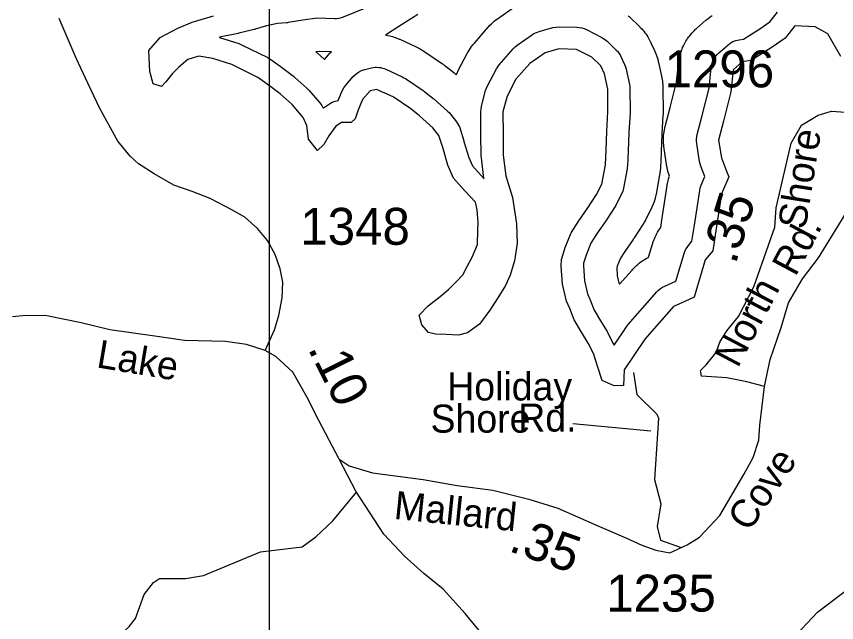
# Model space of a CAD drawing. Extents: x 1113032 to 1302912, y 664689 to 832535.
# Drawn here: x 1146811 to 1149593, y 736082 to 738136 of the extents above; entities that cross this region are included whole.
import ezdxf

# ---------------------------------------------------------------- set-up
doc = ezdxf.new("R2010")
doc.units = 0
for name, color, linetype in [('Exist Hydrographic Buffer Line', 7, 'Continuous'), ('Exist Hydrographic Lake Shore', 7, 'Continuous'), ('Exist Road Non-System Type 51', 7, 'Continuous'), ('Exist Road Non-System Type 51 Label', 7, 'Continuous'), ('Exist Road Secondary Mileage Hundredths English Label', 7, 'Continuous'), ('Exist Road Secondary Type 51 Attributed', 7, 'Continuous'), ('Exist Road Secondary Type 51 Label', 7, 'Continuous'), ('Exist Road Secondary Type 51 Number Label', 7, 'Continuous'), ('Map Preparation Inset Cut Line', 7, 'Continuous')]:
    doc.layers.add(name, color=color, linetype=linetype)

msp = doc.modelspace()

# ---------------------------------------------------------------- linework, layer by layer
at = {"layer": 'Exist Hydrographic Buffer Line'}
for points in [[(1147992, 738162.3), (1147919, 738133.4), (1147911.9, 738130.9), (1147904.6, 738129.2), (1147897.1, 738128.3), (1147889.6, 738128.1), (1147830.9, 738129.5), (1147782.4, 738122.7), (1147733.1, 738114.9), (1147730.6, 738114.6), (1147728.2, 738114.3), (1147696.8, 738111.5), (1147659.3, 738103.6), (1147621.2, 738092.4), (1147619.5, 738091.9), (1147617.7, 738091.4), (1147565.3, 738078.7), (1147564, 738078.4), (1147562.6, 738078.1), (1147499.4, 738065.2), (1147500.2, 738065), (1147564.9, 738043.8), (1147569.7, 738042), (1147574.4, 738039.9), (1147663.1, 737996.5), (1147668.6, 737993.5), (1147673.9, 737990.1), (1147712.9, 737962.1), (1147713.7, 737961.5), (1147714.5, 737960.9), (1147750.9, 737933.3), (1147753.4, 737931.4), (1147755.7, 737929.4), (1147795.8, 737893.4), (1147799.3, 737890), (1147802.6, 737886.4), (1147840.1, 737842.8), (1147846.5, 737834), (1147851.1, 737825.5), (1147852.8, 737826.7), (1147872.7, 737839.8), (1147882.2, 737845.1), (1147892.4, 737849), (1147901.8, 737851.1), (1147916.3, 737884.2), (1147921.6, 737894.2), (1147928.3, 737903.2), (1147953.5, 737932.4), (1147961.8, 737940.5), (1147971.1, 737947.2), (1147981.4, 737952.5), (1147992.4, 737956.1), (1148014.7, 737961.6), (1148020.9, 737962.8), (1148027.2, 737963.5), (1148033.5, 737963.7), (1148039.8, 737963.4), (1148046.1, 737962.5), (1148052.2, 737961.1), (1148058.3, 737959.2), (1148064.1, 737956.8), (1148119.8, 737931), (1148125.1, 737928.3), (1148130.2, 737925.1), (1148190.3, 737884.6), (1148192.6, 737883), (1148194.9, 737881.3), (1148224.8, 737857.6), (1148226.3, 737856.4), (1148227.8, 737855.1), (1148273.1, 737815.2), (1148278.2, 737810.3), (1148282.8, 737804.9), (1148303.2, 737778.7), (1148307.1, 737773.2), (1148310.4, 737767.5), (1148313.3, 737761.4), (1148315.5, 737755.2), (1148328.5, 737714.1), (1148328.7, 737713.4), (1148328.9, 737712.7), (1148344.9, 737657.9), (1148357.5, 737629.5), (1148386.7, 737597), (1148396.9, 737585.8), (1148396.7, 737587), (1148387.9, 737656.6), (1148387.5, 737660.8), (1148387.3, 737665), (1148386.4, 737735.9), (1148386.3, 737736.4), (1148386.3, 737736.8), (1148386.2, 737812.5), (1148386.8, 737822), (1148388.6, 737831.4), (1148402.4, 737884.4), (1148405, 737892.7), (1148408.6, 737900.6), (1148438.8, 737957.8), (1148443.3, 737965.3), (1148448.6, 737972.2), (1148495.5, 738026), (1148502, 738032.6), (1148509.3, 738038.4), (1148561, 738074.2), (1148566.3, 738077.6), (1148571.9, 738080.5), (1148577.7, 738083), (1148583.7, 738084.9), (1148630.3, 738097.9), (1148641.1, 738100), (1148652, 738100.6), (1148712.1, 738099.3), (1148720.5, 738098.7), (1148728.7, 738097.1), (1148736.7, 738094.6), (1148744.4, 738091.2), (1148796.1, 738065), (1148805.7, 738059.2), (1148814.3, 738052), (1148845.4, 738021.9), (1148850.1, 738016.9), (1148854.3, 738011.5), (1148858, 738005.8), (1148861.2, 737999.7), (1148873.6, 737973), (1148876.8, 737965.2), (1148879, 737957), (1148890, 737905.4), (1148891.2, 737898), (1148891.6, 737890.4), (1148892.2, 737814.3), (1148892.2, 737811.6), (1148892.1, 737808.9), (1148887.8, 737742.3), (1148885.7, 737680.8), (1148885.7, 737680.3), (1148885.7, 737679.8), (1148883.2, 737629.6), (1148882.8, 737624.7), (1148882.1, 737619.8), (1148870.1, 737554.1), (1148867.4, 737543.6), (1148863.2, 737533.5), (1148845.5, 737498.8), (1148843.6, 737495.3), (1148841.5, 737491.8), (1148811.9, 737446.6), (1148811.3, 737445.6), (1148810.6, 737444.7), (1148780.8, 737401.9), (1148759.1, 737367.9), (1148742.9, 737327.6), (1148734.3, 737300.2), (1148734.1, 737291), (1148737.1, 737240.1), (1148747.7, 737196.3), (1148756, 737178.4), (1148757.3, 737175.6), (1148758.4, 737172.8), (1148770.4, 737140.2), (1148791.6, 737104.9), (1148814.1, 737068.5), (1148815.7, 737065.7), (1148817.2, 737063), (1148835.3, 737027.5), (1148837.7, 737022.2), (1148837.8, 737022), (1148879.8, 737084.3), (1148882.6, 737088.2), (1148885.6, 737091.9), (1148983.1, 737202.9), (1148988.9, 737208.8), (1148995.3, 737214), (1149002.2, 737218.5), (1149009.5, 737222.2), (1149047.5, 737238.7), (1149075.5, 737332.8), (1149078.1, 737340), (1149081.4, 737347), (1149085.4, 737353.6), (1149090.1, 737359.8), (1149102.1, 737374), (1149110.5, 737428.8), (1149128.5, 737546.1), (1149130.4, 737555.2), (1149133.5, 737564), (1149146.1, 737593.8), (1149132.2, 737628.9), (1149129.7, 737636.7), (1149127.9, 737644.7), (1149118.3, 737705), (1149117.5, 737712.7), (1149117.4, 737720.3), (1149118.2, 737728), (1149119.7, 737735.5), (1149136.2, 737799.7), (1149160, 737893.3), (1149167.3, 737963.2), (1149168.3, 737970.1), (1149170, 737976.9), (1149172.3, 737983.5), (1149175.2, 737989.8), (1149178.7, 737995.9), (1149182.8, 738001.6), (1149187.3, 738006.9), (1149192.3, 738011.7), (1149223.2, 738038.9), (1149231.8, 738045.4), (1149241.2, 738050.7), (1149251.4, 738054.5), (1149261.9, 738056.8), (1149276.8, 738059), (1149332.4, 738094), (1149366.2, 738117.8), (1149392.7, 738150.8)], [(1148171.9, 738142.3), (1148107.8, 738102.1), (1148066, 738075), (1148063.7, 738073.5), (1148063.1, 738073.2), (1148066.2, 738072.7), (1148070.8, 738071.7), (1148077, 738070.3), (1148081.6, 738069.2), (1148086.1, 738067.9), (1148092.1, 738066), (1148096.6, 738064.4), (1148101, 738062.7), (1148106.8, 738060.3), (1148109, 738059.4), (1148111.2, 738058.4), (1148166.8, 738032.6), (1148168.9, 738031.7), (1148170.9, 738030.7), (1148176.2, 738028), (1148180.1, 738025.8), (1148183.9, 738023.6), (1148189, 738020.4), (1148190.9, 738019.2), (1148192.8, 738018), (1148252.9, 737977.5), (1148253.7, 737976.9), (1148254.6, 737976.3), (1148257, 737974.7), (1148258.7, 737973.4), (1148260.4, 737972.2), (1148262.7, 737970.4), (1148263.5, 737969.8), (1148264.4, 737969.1), (1148294.3, 737945.4), (1148294.9, 737945), (1148295.4, 737944.5), (1148297, 737943.3), (1148298.1, 737942.3), (1148299.2, 737941.4), (1148300.7, 737940.1), (1148301.3, 737939.6), (1148301.8, 737939.2), (1148302.8, 737938.3), (1148303.1, 737939), (1148306.7, 737946.9), (1148308, 737949.8), (1148309.5, 737952.7), (1148339.7, 738010), (1148341.2, 738012.8), (1148342.8, 738015.7), (1148347.3, 738023.1), (1148350.9, 738028.6), (1148354.7, 738033.8), (1148360, 738040.7), (1148362.1, 738043.3), (1148364.2, 738045.7), (1148411.1, 738099.6), (1148413.4, 738102.2), (1148415.8, 738104.7), (1148422.3, 738111.3), (1148427.3, 738116), (1148432.6, 738120.5), (1148439.9, 738126.2), (1148442.6, 738128.3), (1148445.4, 738130.4), (1148497.1, 738166.2)], [(1148886, 738138.1), (1148889.2, 738135.3), (1148892.3, 738132.5), (1148923.3, 738102.4), (1148925.1, 738100.6), (1148926.9, 738098.7), (1148931.6, 738093.7), (1148935.1, 738089.9), (1148938.3, 738086), (1148942.5, 738080.6), (1148945.6, 738076.5), (1148948.5, 738072.2), (1148952.2, 738066.5), (1148954.9, 738062.1), (1148957.3, 738057.6), (1148960.5, 738051.5), (1148961.7, 738049.3), (1148962.8, 738046.9), (1148975.2, 738020.3), (1148976.5, 738017.4), (1148977.7, 738014.5), (1148980.8, 738006.6), (1148983, 738000.7), (1148984.8, 737994.6), (1148987, 737986.4), (1148987.8, 737983.4), (1148988.5, 737980.3), (1148999.5, 737928.7), (1149000.1, 737926), (1149000.5, 737923.2), (1149001.7, 737915.7), (1149002.5, 737910.1), (1149003, 737904.5), (1149003.4, 737897), (1149003.5, 737894.1), (1149003.6, 737891.3), (1149004.2, 737815.2), (1149004.2, 737814.2), (1149004.2, 737813.2), (1149004.2, 737810.5), (1149004.1, 737808.5), (1149004.1, 737806.5), (1149003.9, 737803.8), (1149003.9, 737802.8), (1149003.8, 737801.8), (1148999.7, 737736.8), (1148997.6, 737677), (1148997.6, 737676.8), (1148997.6, 737676.6), (1148997.6, 737676), (1148997.6, 737675.6), (1148997.6, 737675.2), (1148997.6, 737674.7), (1148997.5, 737674.5), (1148997.5, 737674.3), (1148995.1, 737624.1), (1148995, 737622.3), (1148994.8, 737620.5), (1148994.4, 737615.6), (1148994.1, 737611.9), (1148993.6, 737608.2), (1148992.9, 737603.4), (1148992.6, 737601.6), (1148992.3, 737599.7), (1148980.3, 737534), (1148979.5, 737530), (1148978.5, 737526.1), (1148975.8, 737515.5), (1148973.5, 737507.8), (1148970.6, 737500.2), (1148966.4, 737490.2), (1148964.8, 737486.5), (1148963, 737482.8), (1148945.4, 737448.1), (1148944.7, 737446.8), (1148944, 737445.4), (1148942, 737441.8), (1148940.5, 737439.2), (1148939, 737436.6), (1148936.9, 737433.1), (1148936.1, 737431.8), (1148935.2, 737430.6), (1148905.7, 737385.4), (1148905.5, 737385), (1148905.2, 737384.6), (1148904.6, 737383.7), (1148904.1, 737382.9), (1148903.6, 737382.2), (1148902.9, 737381.2), (1148902.7, 737380.9), (1148902.4, 737380.5), (1148874, 737339.8), (1148859.2, 737316.5), (1148848.5, 737290), (1148846.7, 737284.2), (1148848.3, 737256.7), (1148853.9, 737233.5), (1148856.3, 737228.3), (1148899, 737276.8), (1148901.1, 737279.1), (1148903.2, 737281.3), (1148908.9, 737287.2), (1148913.4, 737291.5), (1148918, 737295.5), (1148924.4, 737300.7), (1148929.2, 737304.4), (1148934.3, 737307.9), (1148941.2, 737312.4), (1148946.4, 737315.6), (1148951.8, 737318.5), (1148954.8, 737320), (1148968.1, 737364.7), (1148969, 737367.5), (1148969.9, 737370.2), (1148972.5, 737377.5), (1148974.6, 737382.9), (1148976.9, 737388.2), (1148980.2, 737395.1), (1148982.8, 737400.3), (1148985.7, 737405.3), (1148989.7, 737411.9), (1148992.8, 737416.7), (1148996, 737421.1), (1148999.8, 737445.8), (1149017.8, 737563), (1149018.3, 737566.4), (1149019, 737569.9), (1149021, 737578.9), (1149022.7, 737585.7), (1149024.8, 737592.3), (1149025.6, 737594.7), (1149023.4, 737601.3), (1149021.6, 737607.1), (1149020.2, 737613), (1149018.5, 737621), (1149017.9, 737624), (1149017.3, 737627), (1149007.7, 737687.4), (1149007.3, 737690.2), (1149006.9, 737693), (1149006.1, 737700.7), (1149005.7, 737706.4), (1149005.5, 737712.1), (1149005.4, 737719.8), (1149005.6, 737725.5), (1149006, 737731.2), (1149006.7, 737738.9), (1149007.4, 737744.6), (1149008.4, 737750.2), (1149009.9, 737757.7), (1149010.5, 737760.5), (1149011.2, 737763.3), (1149027.7, 737827.4), (1149049.4, 737913), (1149055.9, 737974.9), (1149056.2, 737977.5), (1149056.6, 737980.1), (1149057.6, 737987), (1149058.5, 737992.1), (1149059.7, 737997.2), (1149061.3, 738004), (1149062.7, 738009), (1149064.3, 738014), (1149066.6, 738020.5), (1149068.5, 738025.4), (1149070.5, 738030.2), (1149073.4, 738036.5), (1149075.7, 738041.2), (1149078.2, 738045.8), (1149081.7, 738051.8), (1149084.4, 738056.3), (1149087.3, 738060.6), (1149091.4, 738066.3), (1149094.5, 738070.5), (1149097.8, 738074.5), (1149102.3, 738079.8), (1149105.8, 738083.7), (1149109.5, 738087.4), (1149114.5, 738092.3), (1149116.4, 738094), (1149118.3, 738095.8), (1149149.2, 738123), (1149152.2, 738125.6), (1149155.4, 738128.1), (1149164, 738134.6), (1149170.6, 738139.3)]]:
    msp.add_lwpolyline(points, dxfattribs=at)
msp.add_lwpolyline([(1147855.5, 737990.3), (1147868.9, 738005.7), (1147871.8, 738008.9), (1147874.8, 738012), (1147879.2, 738016.3), (1147837.5, 738017.3), (1147826.9, 738015.9), (1147828.8, 738014.3), (1147829.7, 738013.5), (1147830.5, 738012.7)], close=True, dxfattribs=at)
at = {"layer": 'Exist Hydrographic Lake Shore'}
for points in [[(1148302.5, 737236.2), (1148324.6, 737260.5), (1148339.9, 737288.4), (1148356.4, 737320.2), (1148374.2, 737363.7), (1148375.6, 737412.2), (1148376.5, 737437.8), (1148373.6, 737480.6), (1148367.6, 737506.6), (1148331.1, 737546.6), (1148293.7, 737588.2), (1148274.3, 737632.1), (1148256.9, 737691.6), (1148244, 737732.6), (1148223.6, 737758.9), (1148178.3, 737798.8), (1148148.3, 737822.5), (1148088.3, 737863), (1148032.6, 737888.7), (1148010.2, 737883.3), (1147985, 737854.1), (1147968.6, 737816.6), (1147959.8, 737788.5), (1147945.8, 737777.1), (1147913.9, 737777.1), (1147894, 737764.1), (1147870.8, 737731), (1147853.5, 737701.9), (1147832.1, 737681.2), (1147802, 737719.7), (1147795.5, 737766.1), (1147783.1, 737794), (1147745.7, 737837.6), (1147705.6, 737873.6), (1147669.2, 737901.1), (1147630.2, 737929.1), (1147541.5, 737972.5), (1147476.8, 737993.7), (1147429.4, 738000.8), (1147392.2, 737990.3), (1147361.8, 737964.3), (1147340, 737942.8), (1147317.5, 737914.5), (1147302.9, 737898.3), (1147275.1, 737907.6), (1147263.8, 737949.5), (1147259.7, 738020.7), (1147298.9, 738064.1), (1147358.9, 738096.5), (1147407.5, 738115.9), (1147479, 738137.6)], [(1149607, 738000.7), (1149562.8, 738077.1), (1149520.1, 738100.3), (1149451.1, 738103.8), (1149418, 738062.6), (1149374, 738031.6), (1149303.3, 737987.1), (1149272.7, 737982.6), (1149241.9, 737955.4), (1149234, 737880.1), (1149208.9, 737781.2), (1149192.4, 737716.9), (1149202, 737656.5), (1149219.5, 737612.2), (1149227.1, 737592.7), (1149202.6, 737534.8), (1149184.7, 737417.4), (1149173, 737341.7), (1149147.3, 737311.4), (1149109.6, 737184.7), (1149078.1, 737170.3), (1149039.5, 737153.4), (1148942, 737042.4), (1148872.4, 736939), (1148870.2, 736885.4), (1148838.6, 736884.2), (1148797.5, 736902.5), (1148782.2, 736951.5), (1148768.4, 736993.5), (1148750.4, 737029), (1148727.5, 737065.9), (1148702.5, 737107.7), (1148688, 737146.8), (1148676.5, 737171.4), (1148662.6, 737228.9), (1148659, 737289.8), (1148659.6, 737312.6), (1148672.2, 737352.9), (1148692.1, 737402.4), (1148718.4, 737443.6), (1148749.1, 737487.6), (1148778.7, 737532.8), (1148796.3, 737567.5), (1148808.3, 737633.3), (1148810.8, 737683.4), (1148812.9, 737745.9), (1148817.2, 737813.7), (1148816.6, 737889.8), (1148805.6, 737941.4), (1148793.2, 737968), (1148762.2, 737998.1), (1148710.5, 738024.3), (1148650.4, 738025.6), (1148603.8, 738012.6), (1148552.1, 737976.8), (1148505.1, 737922.9), (1148475, 737865.6), (1148461.2, 737812.6), (1148461.3, 737736.9), (1148462.3, 737666), (1148471.1, 737596.4), (1148493.2, 737522.6), (1148507.5, 737433.4), (1148509.5, 737366.5), (1148499.9, 737308.3), (1148485.6, 737258.9), (1148469.2, 737224.6), (1148444.1, 737182.6), (1148417, 737141.1), (1148381.2, 737093.4), (1148341.1, 737064), (1148310.7, 737055.6), (1148267.9, 737058.7), (1148231.8, 737059), (1148208.8, 737065.6), (1148186.2, 737090.6), (1148176.5, 737123.7), (1148207.8, 737155.4), (1148248.6, 737186.7), (1148276.8, 737210.3), (1148302.5, 737236.2)], [(1149438.6, 736022.9), (1149527.6, 736117.4), (1149636.3, 736200.3)]]:
    msp.add_lwpolyline(points, dxfattribs=at)
at = {"layer": 'Exist Road Non-System Type 51'}
for points in [[(1148903.4, 736929.1), (1148915.3, 736854.7), (1148983.3, 736788.6), (1148988.9, 736774.4), (1148975.2, 736566.6), (1148996.8, 736484.1), (1148984.5, 736408.3), (1148995, 736361.2), (1149066, 736337.2)], [(1146874, 735982.4), (1146909.6, 735973.1), (1146986.9, 735966.3), (1147030.9, 735969.1), (1147119.8, 735998.8), (1147193.8, 736068.5), (1147214.7, 736096), (1147244.8, 736177.2), (1147276.2, 736218.5), (1147296.5, 736231.9), (1147384.4, 736231.5), (1147445, 736241.7), (1147639.3, 736322.2), (1147779.8, 736338.4), (1147826.8, 736372.9), (1147884.3, 736427.3), (1147964, 736524)]]:
    msp.add_lwpolyline(points, dxfattribs=at)
at = {"layer": 'Exist Road Non-System Type 51 Label'}
msp.add_lwpolyline([(1148697.5, 736756.5), (1148962.6, 736732.2)], dxfattribs=at)
at = {"layer": 'Exist Road Secondary Type 51 Attributed'}
for points in [[(1147654.9, 737004.6), (1147686.1, 737074.3), (1147700.5, 737122.4), (1147712.5, 737182.4), (1147714.9, 737235.3), (1147705.3, 737280.9), (1147688.5, 737329), (1147662.1, 737377), (1147628.5, 737417.9), (1147585.3, 737456.3), (1147542.1, 737480.3), (1147467.6, 737518.8), (1147407.6, 737542.8), (1147345.2, 737564.4), (1147278, 737602.8), (1147225.1, 737636.5), (1147196.3, 737662.9), (1147155.5, 737713.4), (1147093.1, 737826.3), (1147045.1, 737927.2), (1147013.8, 737994.4), (1146956.2, 738129)], [(1147654.9, 737004.6), (1147686.1, 737074.3), (1147700.5, 737122.4), (1147712.5, 737182.4), (1147714.9, 737235.3), (1147705.3, 737280.9), (1147688.5, 737329), (1147662.1, 737377), (1147628.5, 737417.9), (1147585.3, 737456.3), (1147542.1, 737480.3), (1147467.6, 737518.8), (1147407.6, 737542.8), (1147345.2, 737564.4), (1147278, 737602.8), (1147225.1, 737636.5), (1147196.3, 737662.9), (1147155.5, 737713.4), (1147093.1, 737826.3), (1147045.1, 737927.2), (1147013.8, 737994.4), (1146956.2, 738129)], [(1149347.8, 736882.3), (1149287.7, 736897.5), (1149219.8, 736911.6), (1149133.9, 736916.8), (1149131.4, 736936), (1149150.4, 736956), (1149183.9, 736997.6), (1149196.7, 737032.2), (1149219.8, 737070.7), (1149259.5, 737119.4), (1149312.1, 737219.5), (1149383.6, 737421.7), (1149387.5, 737487.6), (1149438.9, 737706.1), (1149473.5, 737767.5), (1149530.4, 737801.8), (1149574.9, 737814.7), (1149764.4, 737801), (1149862.6, 737806.3), (1149918.6, 737798.9), (1150001.8, 737772.3), (1150066, 737740.6), (1150117.2, 737703.4)], [(1149347.8, 736882.3), (1149367, 736973.4), (1149404.2, 737082.4), (1149429.9, 737165.8), (1149476.9, 737247.3), (1149530.8, 737317.9), (1149609, 737444.9), (1149655.1, 737521.8), (1149692.3, 737543.6), (1149787.7, 737554.4), (1149838.4, 737548.8), (1149965.7, 737477.3), (1150058.9, 737412.8), (1150132.7, 737378.4), (1150236.6, 737360.3), (1150498.1, 737356.4)], [(1147654.9, 737004.6), (1147590.8, 737024.3), (1147520.5, 737034.9), (1147381.4, 737037.8), (1147280, 737052.6), (1147127.3, 737074.3), (1147030.5, 737097.3), (1146914.2, 737121.3), (1146844.6, 737122.7), (1146797.6, 737118.1)], [(1147654.9, 737004.6), (1147590.8, 737024.3), (1147520.5, 737034.9), (1147381.4, 737037.8), (1147280, 737052.6), (1147127.3, 737074.3), (1147030.5, 737097.3), (1146914.2, 737121.3), (1146844.6, 737122.7), (1146797.6, 737118.1)], [(1147905.4, 736636.1), (1147836.1, 736766.9), (1147795.9, 736847.3), (1147748.1, 736930.2), (1147690.8, 736984.1), (1147654.9, 737004.6)], [(1147905.4, 736636.1), (1147939, 736613.7), (1148018.9, 736589.4), (1148190.6, 736567.6), (1148306, 736547.1), (1148426.5, 736530.4), (1148548.7, 736500.6), (1148646.9, 736470), (1148780, 736411.3), (1148877.4, 736369.4), (1148932.2, 736344.1), (1148979.4, 736328.1), (1149026.6, 736318.8), (1149085.3, 736346.1), (1149127.6, 736371.8), (1149196.8, 736444.9), (1149277.8, 736584.2), (1149309.5, 736641.3), (1149329.1, 736700.6), (1149332.4, 736750.8), (1149347.8, 736882.3)], [(1149107.9, 735268.3), (1148972.9, 735265.7), (1148869.5, 735276), (1148765.2, 735339.3), (1148717.3, 735395.7), (1148692, 735470), (1148675.6, 735657.1), (1148671.4, 735688.7), (1148645.1, 735725.3), (1148534.7, 735842.9), (1148485.2, 735909.6), (1148449.3, 735972), (1148333.2, 736113.6), (1148257.9, 736195.7), (1148192.6, 736248.2), (1148127.7, 736307), (1148057.6, 736382.3), (1147961.9, 736527.3), (1147905.4, 736636.1)]]:
    msp.add_lwpolyline(points, dxfattribs=at)
at = {"layer": 'Map Preparation Inset Cut Line'}
msp.add_lwpolyline([(1223351.7, 748878.2), (1147668.5, 748878.2), (1147668.5, 704629.7), (1208143, 704629.7), (1208143, 720169.6), (1223351.7, 720169.6)], close=True, dxfattribs=at)

# ---------------------------------------------------------------- texts
at = {"layer": 'Exist Road Non-System Type 51 Label'}
for s, p in [('Holiday', (1148272, 736834.8)), ('Shore', (1148215.5, 736725.8)), ('Rd.', (1148512.9, 736729.5))]:
    msp.add_text(s, height=95, dxfattribs=at).set_placement(p)
at = {"layer": 'Exist Road Secondary Mileage Hundredths English Label'}
for s, rotation, p in [('.35', 72.5993, (1149249.7, 737293.2)), ('.10', 296.5499, (1147798.1, 737011)), ('.35', 340.4756, (1148476.5, 736325.8))]:
    msp.add_text(s, height=125, rotation=rotation, dxfattribs=at).set_placement(p)
at = {"layer": 'Exist Road Secondary Type 51 Label'}
for s, rotation, p in [('Shore', 80.9632, (1149487, 737412)), ('Rd.', 61.8883, (1149452.9, 737251.6)), ('North', 62.1988, (1149257.4, 736941.7)), ('Lake', 350.4561, (1147079.7, 736947.5)), ('Cove', 55.9682, (1149295.6, 736386.4)), ('Mallard', 354.151, (1148088.8, 736433.9))]:
    msp.add_text(s, height=95, rotation=rotation, dxfattribs=at).set_placement(p)
at = {"layer": 'Exist Road Secondary Type 51 Number Label'}
for s, p in [('1296', (1149009, 737895.6)), ('1348', (1147773.7, 737362.3)), ('1235', (1148811.3, 736119.6))]:
    msp.add_text(s, height=125, dxfattribs=at).set_placement(p)

doc.saveas('drawing.dxf')
